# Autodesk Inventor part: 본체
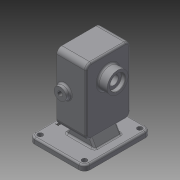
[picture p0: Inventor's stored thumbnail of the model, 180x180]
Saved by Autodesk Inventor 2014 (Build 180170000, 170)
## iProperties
Created: 2020-04
Part Number: 본체
Material: Generic
Document SubType Name: Modeling
Designer: kh
Density: 1 g/cm^3
Appearance: Default
Author: kh
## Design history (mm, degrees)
sketch "스케치1"
  geometry: L1 (-50, -60)-(50, -60); L2 (50, -60)-(50, 60); L3 (50, 60)-(-50, 60); L4 (-50, 60)-(-50, -60); L5 (-50, -60)-(50, 60); L6 (50, -60)-(-50, 60); 1 further point
  constraints: 12 end point, 2 midpoint, 2 parallel, 1 horizontal, 1 perpendicular
  dimensions: "d0" = 100 distance of L3.end L2.end; "d1" = 120 distance of L2.end L1.end
extrude "돌출1" new body sketch "스케치1" distance "d2" = 10; taper "d3" = 0 deg
node "작업 평면1"
sketch "스케치2"
  geometry: L1 (0, 60)-(90, 60); L2 (30, 100)-(150, 100); L3 (150, 100)-(150, 20); L4 (150, 20)-(30, 20); L5 (30, 20)-(30, 100); L6 (30, 100)-(150, 20); L7 (150, 100)-(30, 20)
  constraints: 14 end point, 2 horizontal, 2 midpoint, 2 parallel, 1 perpendicular
  dimensions: "d5" = 90 distance of L1.start L1.end; "d6" = 80 distance of L2.end L3.end; "d7" = 120 distance of L3.end L4.end
extrude "돌출2" join sketch "스케치2" distance "d8" = 53; taper "d9" = 0 deg
sketch "스케치3"
  geometry: L1 (0, 60)-(-112, 60); C1 r 19 at (-112, 60)
  constraints: 2 end point, 1 centre point, 1 coincident, 1 horizontal
  dimensions: "d10" = 112 distance of L1.start L1.end; "d11" = 38 diameter of C1
extrude "돌출3" join sketch "스케치3" distance "d12" = 17; taper "d13" = 0 deg
sketch "스케치4"
  geometry: L1 (30, 100)-(150, 100) reference; L2 (30, 20)-(30, 100) reference; L3 (150, 20)-(30, 20) reference; L4 (150, 100)-(150, 20) reference; L5 (0, 60)-(150, 60); L6 (112, 60)-(68, 60); L7 (112, 84)-(68, 84); L8 (68, 36)-(112, 36); L9 (112, 100)-(112, 20); L10 (0, 0)-(0, 120) reference; A1 r 24 centre (112, 60) between (112, 36) and (112, 84); A2 r 24 centre (68, 60) between (68, 84) and (68, 36); 1 further point
  constraints: 12 end point, 4 point on circle, 4 point on line, 4 tangent, 3 midpoint, 2 centre point, 1 parallel, 1 perpendicular
  dimensions: "d14" = 92 dimension on A2 A1; "d15" = 112 distance between parallel lines of L9 L10; "d16" = 24 radius of A1
extrude "돌출4" cut sketch "스케치4" distance "d17" = 29; taper "d18" = 0 deg
sketch "스케치5"
  geometry: L1 (-50, 131)-(-50, 93) reference; L2 (20, 30)-(20, 150) reference; L3 (-50, 112)-(-9, 112); L4 (-9, 136)-(-9, 112) reference; L5 (-9, 124.5)-(-24, 124.5); L6 (-24, 124.5)-(-24, 120.5); L7 (-24, 120.5)-(-42.7, 120.5); L8 (-42.7, 120.5)-(-42.7, 126); L9 (-42.7, 126)-(-50, 126); L10 (-9, 124.5)-(-9, 112); L11 (-50, 126)-(-50, 112); 1 further point
  constraints: 16 end point, 5 perpendicular, 3 point on line, 2 parallel, 1 collinear, 1 midpoint
  dimensions: "d19" = 25 diameter of L5 L3; "d20" = 17 diameter of L7 L3; "d21" = 28 diameter of L9 L3; "d22" = 15 distance of L5.start L5.end; "d23" = 7.3 distance of L8.end L9.end
revolve "회전1" sketch "스케치5" stored, may be unused: angle "d24" = 90 deg
sketch "스케치6"
  geometry: L1 (-9, 68)-(-9, 44) reference; L2 (-9, 68)-(-9, 112) reference; L3 (-33, 30)-(-33, 150) reference; L4 (-50, 98)-(-50, 126) reference; L5 (-9, 112)-(-50, 112); L6 (-9, 68)-(-33, 68); L7 (-9, 68)-(-9, 80.5); L8 (-24, 80.5)-(-24, 68); L9 (-9, 80.5)-(-24, 80.5); 1 further point
  constraints: 10 end point, 4 point on line, 3 perpendicular, 1 midpoint
  dimensions: "d25" = 44 distance between parallel lines of L6 L5; "d26" = 25 diameter of L9 L6; "d27" = 15 distance of L7.end L8.start
revolve "회전2" sketch "스케치6" stored, may be unused: angle "d28" = 90 deg
sketch "스케치7"
  geometry: L1 (0, 120)-(53, 120) reference; L2 (0, 0)-(53, 0) reference; L3 (14, 120)-(14, 0); L4 (0, 120)-(0, 0) reference; L5 (53, 120)-(53, 0) reference; L6 (0, 60)-(53, 60); L7 (-30, -30)-(70, -30) reference; C1 r 11 at (14, 60); 1 further point
  constraints: 4 end point, 3 midpoint, 3 point on line, 2 perpendicular, 1 centre point
  dimensions: "d29" = 14 distance between parallel lines of L3 L4; "d30" = 90 distance between parallel lines of L6 L7; "d31" = 22 diameter of C1
extrude "돌출5" join sketch "스케치7" distance "d32" = 8; taper "d33" = 0 deg
hole "구멍1" diameter "d36" = 8.917; stored, may be unused: countersink angle "d40" = 90 deg, drill point angle "d42" = 118 deg; dims "d34" = 10, "d35" = 10, "d37" = 6, "d38" = 4, "d39" = 2, "d41" = 8
sketch "스케치8"
  geometry: L1 (150, 20)-(30, 20) reference; L2 (30, 100)-(150, 100) reference; L3 (150, 100)-(150, 20) reference; L4 (30, 20)-(30, 100) reference; L5 (90, 100)-(90, 20); L6 (150, 60)-(30, 60); L7 (39, 91)-(141, 91); L8 (141, 91)-(141, 29); L9 (141, 29)-(39, 29); L10 (39, 29)-(39, 91); L11 (39, 91)-(141, 29); L12 (141, 91)-(39, 29); L13 (68, 91)-(68, 29); L14 (112, 91)-(112, 29); A1 r 24 centre (112, 60) between (112, 36) and (112, 84) reference; A2 r 24 centre (68, 60) between (68, 84) and (68, 36) reference; 10 further points
  constraints: 20 end point, 8 coincident, 7 midpoint, 4 point on line, 3 perpendicular, 2 parallel, 1 horizontal
  dimensions: "d43" = 102 distance of L8.end L9.end; "d44" = 62 distance of L7.end L8.end; "d45" = 22 distance between parallel lines of L14 L5; "d46" = 22 distance between parallel lines of L13 L5
hole "구멍2" sketch "스케치8" at (141, 91), (141, 29), (39, 91), (39, 29), (112, 91), (68, 91), (68, 29), (112, 29) diameter "d47" = 4.459; stored, may be unused: countersink angle "d51" = 90 deg, drill point angle "d53" = 118 deg; dims "d48" = 10, "d49" = 4, "d50" = 2, "d52" = 12
fillet "모깎기1" dims "d54" = 0.5
chamfer "모따기1" distance "d55" = 0.7; stored, may be unused: second distance "d56" = 2, angle "d57" = 30 deg
chamfer "모따기2" distance "d58" = 1; stored, may be unused: second distance "d59" = 2, angle "d60" = 30 deg
fillet "모깎기2" dims "d61" = 3, "d62" = 9
fillet "모깎기3" dims "d63" = 3
fillet "모깎기4" dims "d64" = 10
sketch "스케치9"
  geometry: A1 r 10 centre (-40, 50) between (-40, 60) and (-50, 50) reference; A2 r 10 centre (40, 50) between (50, 50) and (40, 60) reference; A3 r 10 centre (40, -50) between (40, -60) and (50, -50) reference; A4 r 10 centre (-40, -50) between (-50, -50) and (-40, -60) reference; 5 further points
  constraints: 4 coincident
hole "구멍3" sketch "스케치9" at (-40, 50), (40, 50), (40, -50), (-40, -50) diameter "d65" = 9; stored, may be unused: countersink angle "d69" = 90 deg, drill point angle "d71" = 118 deg; dims "d66" = 10, "d67" = 4, "d68" = 2, "d70" = 12
node "작업 평면2"
sketch "스케치10"
  geometry: L1 (70, 30)-(20, 30) reference; L2 (80, 10)-(0, 10) reference; L3 (20, 10)-(31.547, 30); L4 (73, 10)-(61.453, 30); L5 (90, 10)-(90, 0) reference; 1 further point
  constraints: 4 end point, 4 point on line
  dimensions: "d72" = 17 distance from line of L4.start L5; "d73" = 53 distance of L3.start L4.start; "d74" = 60 deg angle of L3 L2; "d75" = 60 deg angle of L2 L4
extrude "돌출6" join sketch "스케치10" stored distance "d76" = 48; taper "d77" = 0 deg
fillet "모깎기5" dims "d78" = 3
fillet "모깎기6" dims "d79" = 3
fillet "모깎기7" dims "d80" = 3
sketch "스케치11"
  geometry: L1 (-36.998, 20.739)-(-36.998, -20.739); L2 (-36.998, -20.739)-(-43.002, -20.739); L3 (-43.002, -20.739)-(-43.002, 20.739); L4 (-43.002, 20.739)-(-36.998, 20.739); L5 (-36.998, 20.739)-(-43.002, -20.739); L6 (-36.998, -20.739)-(-43.002, 20.739); L7 (-50, 50)-(-50, -50) reference; L8 (40, 60)-(-40, 60) reference; 2 further points
  constraints: 4 end point, 1 midpoint, 2 other
  dimensions: "d81" = 10 distance from line of point (-40, 0) L7; "d82" = 60 distance from line of point (-40, 0) L8
feature "엠보싱1" sketch "스케치11" dims "d0" = 100, "d1" = 120, "d83" = 0.5, "d84" = 0
node "솔리드1"
mirror "대칭1"
node "투영된 루프1"
